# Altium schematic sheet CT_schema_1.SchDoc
size 426 x 402 mm
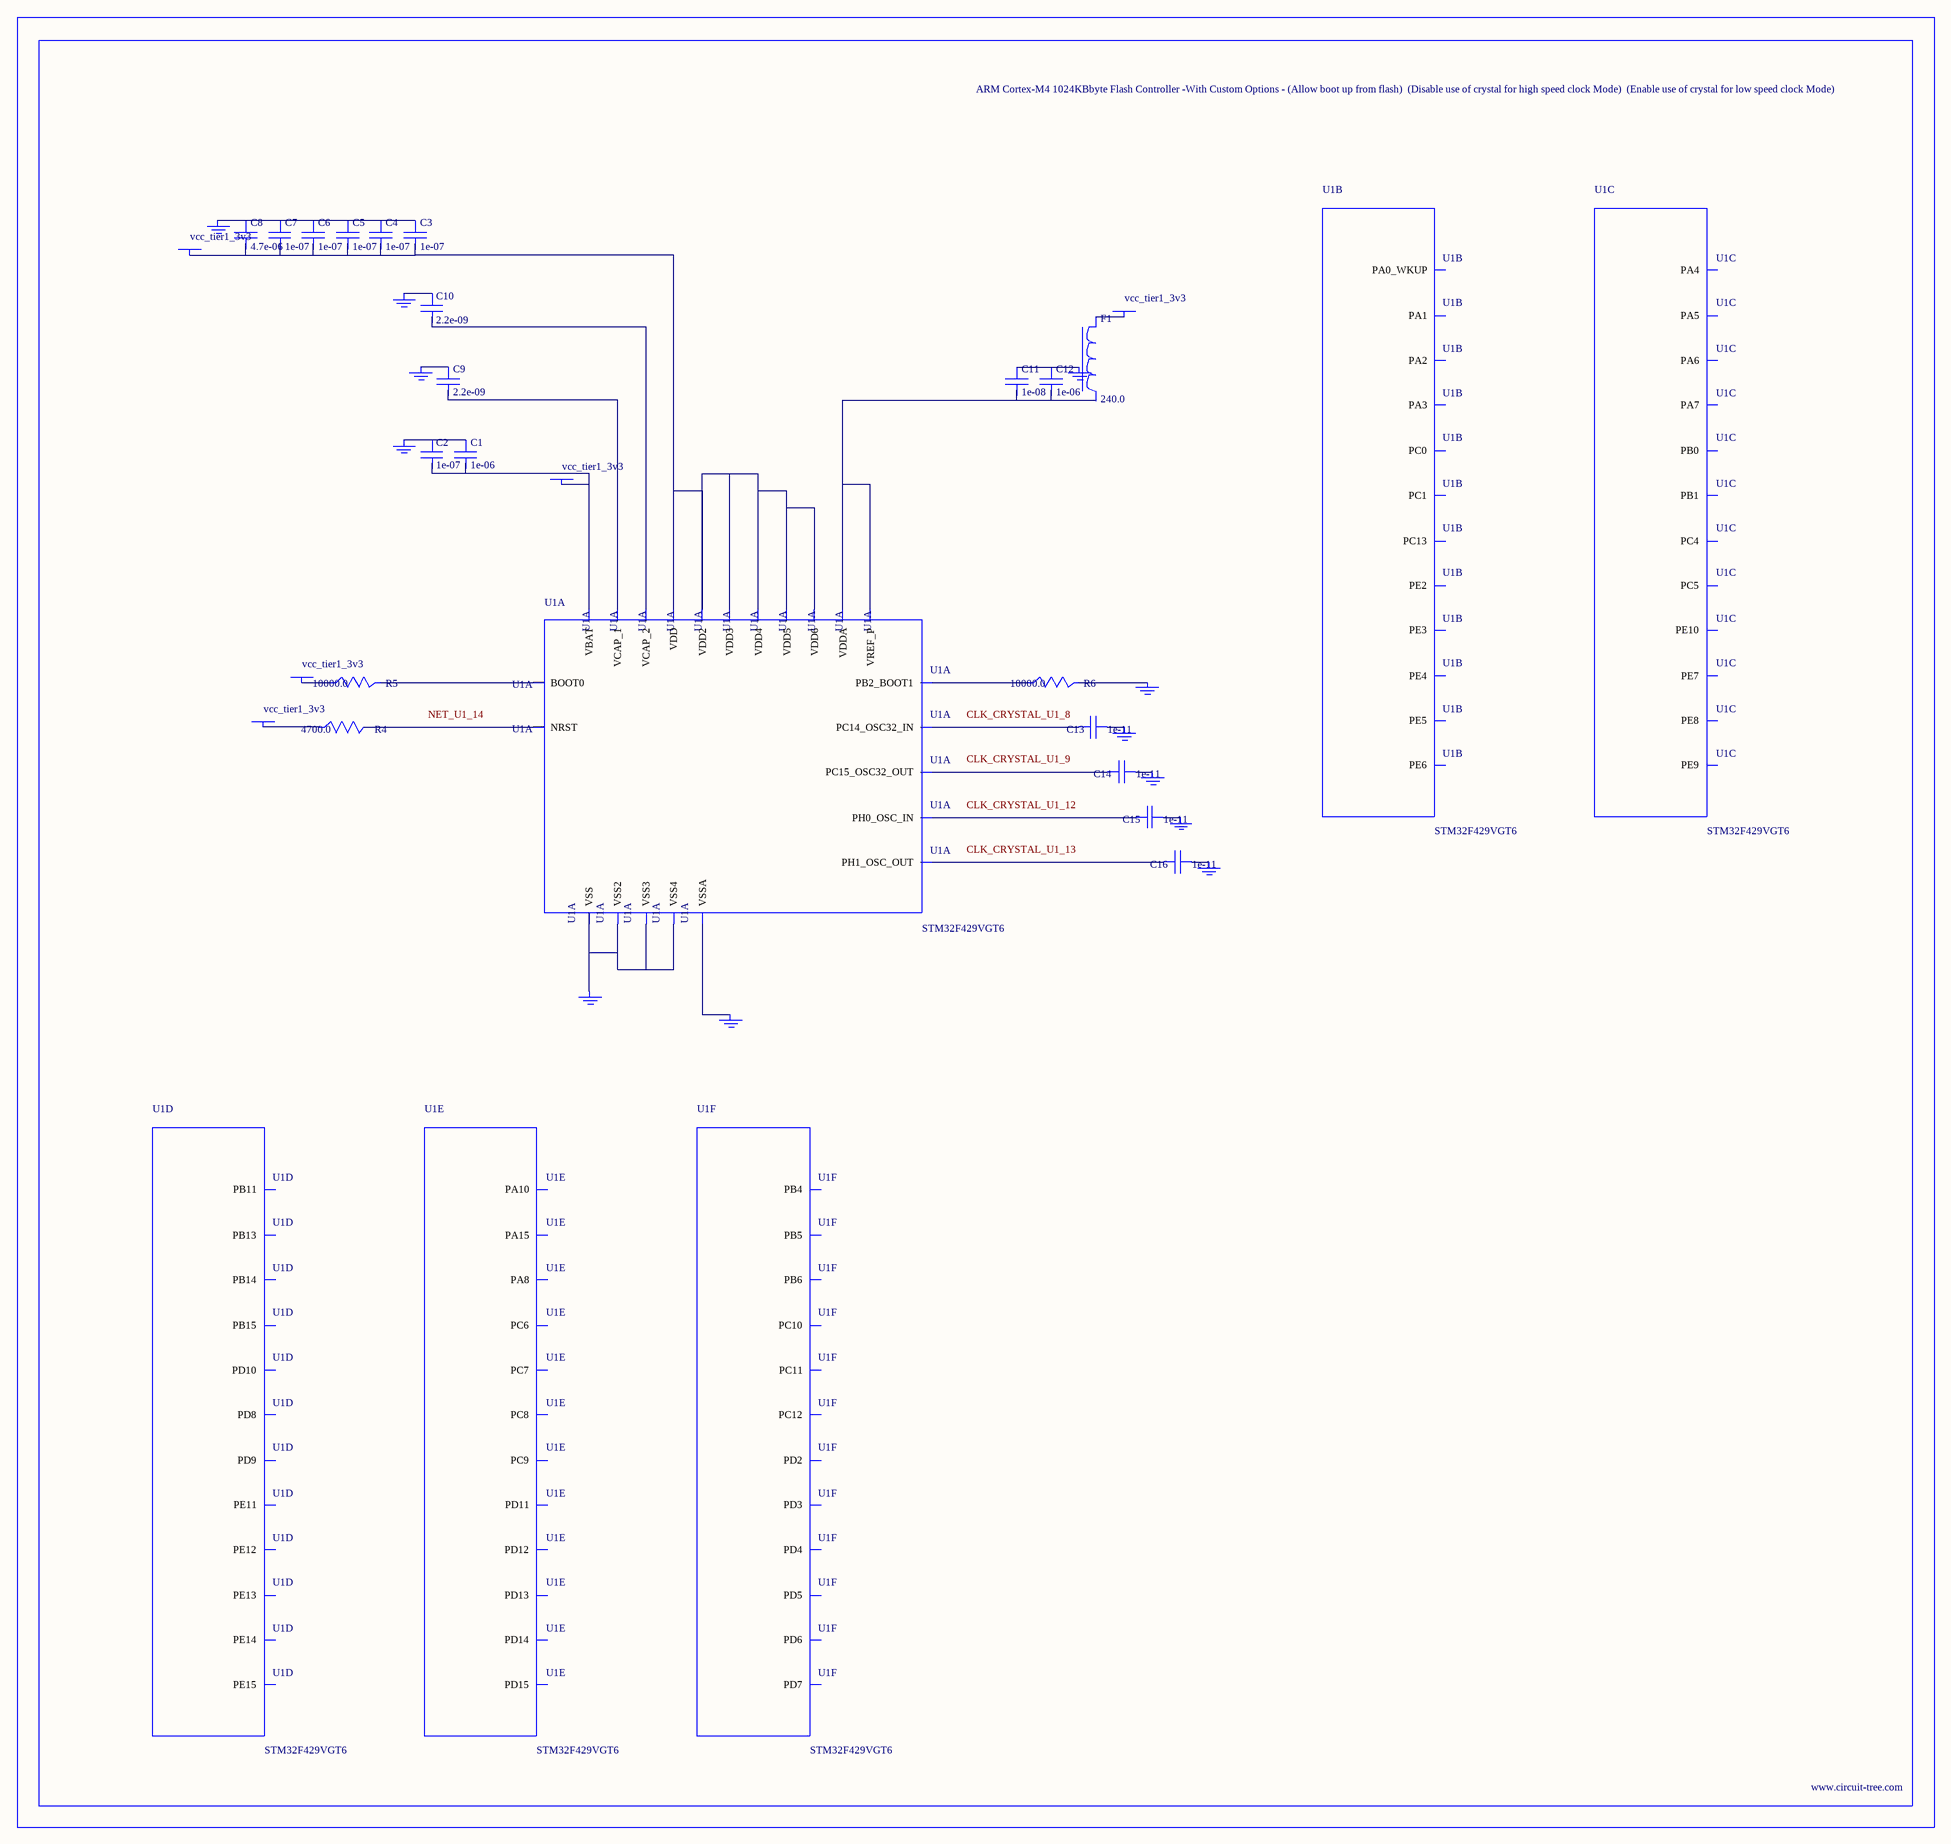
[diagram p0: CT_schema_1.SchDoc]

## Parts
BORDER0  (no value)
C1  1e-06  [C0603]
C2  1e-07  [C0603]
C3  1e-07  [C0603]
C4  1e-07  [C0603]
C5  1e-07  [C0603]
C6  1e-07  [C0603]
C7  1e-07  [C0603]
C8  4.7e-06  [C0603]
C9  2.2e-09  [C0603]
C10  2.2e-09  [C0603]
C11  1e-08  [C0603]
C12  1e-06  [C0603]
C13  1e-11  [C0402]
C14  1e-11  [C0402]
C15  1e-11  [C0402]
C16  1e-11  [C0402]
F1  240.0  [L0603]
GND_INSTANCE_0_0  (no value)
GND_INSTANCE_0_1  (no value)
GND_INSTANCE_0_2  (no value)
GND_INSTANCE_0_3  (no value)
GND_INSTANCE_0_4  (no value)
GND_INSTANCE_0_5  (no value)
GND_INSTANCE_0_6  (no value)
GND_INSTANCE_0_7  (no value)
GND_INSTANCE_0_8  (no value)
GND_INSTANCE_0_9  (no value)
GND_INSTANCE_0_10  (no value)
GND_INSTANCE_0_11  (no value)
POWER_INSTANCE_0_0  vcc_tier1_3v3
POWER_INSTANCE_0_1  vcc_tier1_3v3
POWER_INSTANCE_0_2  vcc_tier1_3v3
POWER_INSTANCE_0_3  vcc_tier1_3v3
POWER_INSTANCE_0_4  vcc_tier1_3v3
R4  4700.0  [R0603]
R5  10000.0  [R0603]
R6  10000.0  [R0603]
U1  STM32F429VGT6  [LQFP100]  (parts A,B,C,D,E,F of 10)

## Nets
NetC1_1: C1.1 C2.1 GND_INSTANCE_0_0.0(GND)
NetC1_2: C1.2 C2.2 POWER_INSTANCE_0_0.0(PWR) U1.6(VBAT)
NetC3_1: C3.1 C4.1 C5.1 C6.1 C7.1 C8.1 GND_INSTANCE_0_3.0(GND)
NetC3_2: C3.2 C4.2 C5.2 C6.2 C7.2 C8.2 POWER_INSTANCE_0_1.0(PWR) U1.11(VDD) U1.19(VDD2) U1.28(VDD3) U1.50(VDD4) U1.75(VDD5) U1.100(VDD6)
NetC9_1: C9.1 GND_INSTANCE_0_9.0(GND)
NetC9_2: C9.2 U1.49(VCAP_1)
NetC10_1: C10.1 GND_INSTANCE_0_10.0(GND)
NetC10_2: C10.2 U1.73(VCAP_2)
NetC11_1: C11.1 C12.1 GND_INSTANCE_0_7.0(GND)
NetC11_2: C11.2 C12.2 U1.21(VREF_P) U1.22(VDDA)
NetC13_1: C13.1 GND_INSTANCE_0_1.0(GND)
NetC13_2: C13.2 U1.8(PC14_OSC32_IN)
NetC14_1: C14.1 GND_INSTANCE_0_2.0(GND)
NetC14_2: C14.2 U1.9(PC15_OSC32_OUT)
NetC15_1: C15.1 GND_INSTANCE_0_4.0(GND)
NetC15_2: C15.2 U1.12(PH0_OSC_IN)
NetC16_1: C16.1 GND_INSTANCE_0_5.0(GND)
NetC16_2: C16.2 U1.13(PH1_OSC_OUT)
NetF1_1: F1.1 POWER_INSTANCE_0_2.0(PWR)
NetGND_INSTANCE_0_6_0: GND_INSTANCE_0_6.0(GND) U1.20(VSSA)
NetGND_INSTANCE_0_8_0: GND_INSTANCE_0_8.0(GND) R6.2
NetGND_INSTANCE_0_11_0: GND_INSTANCE_0_11.0(GND) U1.10(VSS) U1.27(VSS2) U1.74(VSS3) U1.99(VSS4)
NetPOWER_INSTANCE_0_3_0: POWER_INSTANCE_0_3.0(PWR) R5.1
NetPOWER_INSTANCE_0_4_0: POWER_INSTANCE_0_4.0(PWR) R4.1
NetR4_2: R4.2 U1.14(NRST)
NetR5_2: R5.2 U1.94(BOOT0)
NetR6_1: R6.1 U1.37(PB2_BOOT1)

Not connected (* = marked no-connect by the designer): F1 2; U1 1(PE2) 2(PE3) 3(PE4) 4(PE5) 5(PE6) 7(PC13) 15(PC0) 16(PC1) 23(PA0_WKUP) 24(PA1) 25(PA2) 26(PA3) 29(PA4) 30(PA5) 31(PA6) 32(PA7) 33(PC4) 34(PC5) 35(PB0) 36(PB1) 38(PE7) 39(PE8) 40(PE9) 41(PE10) 42(PE11) 43(PE12) 44(PE13) 45(PE14) 46(PE15) 48(PB11) 52(PB13) 53(PB14) 54(PB15) 55(PD8) 56(PD9) 57(PD10) 58(PD11) 59(PD12) 60(PD13) 61(PD14) 62(PD15) 63(PC6) 64(PC7) 65(PC8) 66(PC9) 67(PA8) 69(PA10) 77(PA15) 78(PC10) 79(PC11) 80(PC12) 83(PD2) 84(PD3) 85(PD4) 86(PD5) 87(PD6) 88(PD7) 90(PB4) 91(PB5) 92(PB6)

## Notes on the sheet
- Labels drawn without touching a wire or pin: CLK_CRYSTAL_U1_8, CLK_CRYSTAL_U1_9, CLK_CRYSTAL_U1_12, CLK_CRYSTAL_U1_13, NET_U1_14

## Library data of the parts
BORDER0 = BORDER_PAGE0
C1 C12 = C0603C105K3RACTU
C2-C7 = 06035C104K4Z2A
C8 = GRM188R6YA475KE15D
C9 C10 = 06031C222KAZ2A
C11 = 06035C103K4Z2A
C13-C16 = C0402C100K3GACTU
F1 = Z0603C241ASMST
GND_INSTANCE_0_0-GND_INSTANCE_0_11 = GND
POWER_INSTANCE_0_0-POWER_INSTANCE_0_4 = PWR
R4 = RC0603JR-074K7L
R5 R6 = RC0603JR-0710KL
